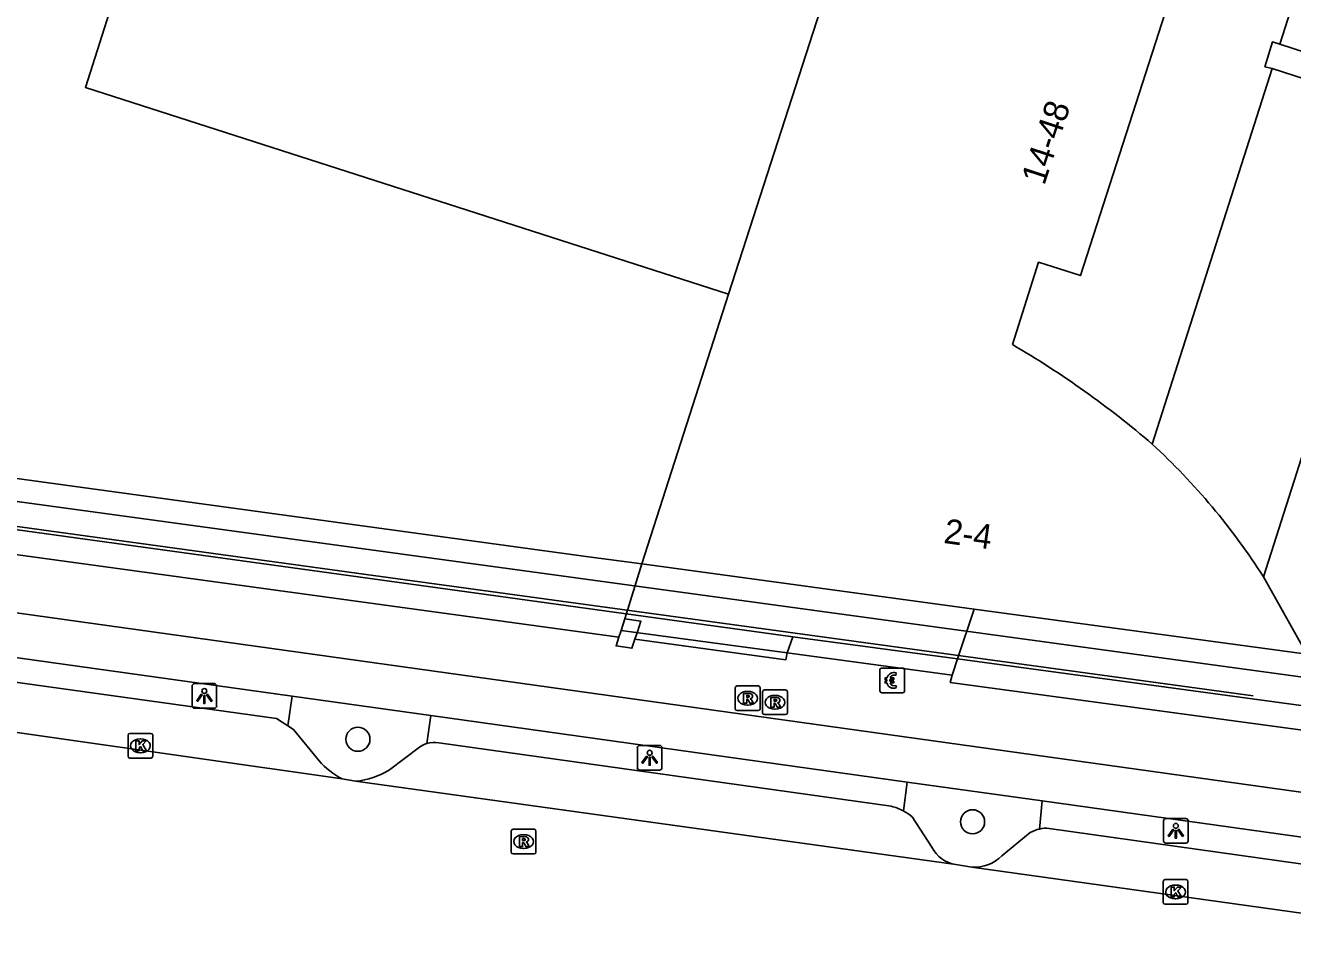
# Model space of a CAD drawing. Extents: x 160676 to 161153, y 383244 to 383713.
# Drawn here: x 160935.4 to 160986.7, y 383253.5 to 383290.1 of the extents above; entities that cross this region are included whole.
import ezdxf

# ---------------------------------------------------------------- set-up
doc = ezdxf.new("R2010")
doc.units = 0
for name, color, linetype in [('IMGEO_Berm_open', 7, 'Continuous'), ('IMGEO_Betaalautomaat', 7, 'Continuous'), ('IMGEO_Boom', 7, 'Continuous'), ('IMGEO_Fietspad_gesloten', 7, 'Continuous'), ('IMGEO_Kolk', 7, 'Continuous'), ('IMGEO_Lichtpunt', 7, 'Continuous'), ('IMGEO_Lijnafwatering', 7, 'Continuous'), ('IMGEO_Muur', 7, 'Continuous'), ('IMGEO_Pand', 7, 'Continuous'), ('IMGEO_Pand_nummerreeks', 7, 'Continuous'), ('IMGEO_Pand_overbouw', 7, 'Continuous'), ('IMGEO_Parkeervlak_open', 7, 'Continuous'), ('IMGEO_Rijbaan_lokaal_gesloten', 7, 'Continuous'), ('IMGEO_Rioolput', 7, 'Continuous'), ('IMGEO_Voetpad_open', 7, 'Continuous')]:
    doc.layers.add(name, color=color, linetype=linetype)

msp = doc.modelspace()

# ---------------------------------------------------------------- linework, layer by layer
at = {"layer": 'IMGEO_Berm_open'}
for points in [[(160946.189, 383262.908), (160946.008, 383261.707)], [(160951.638, 383260.989), (160951.803, 383262.123)], [(160971.094, 383259.424), (160970.944, 383258.256)], [(160976.455, 383257.521), (160976.57, 383258.658)]]:
    msp.add_lwpolyline(points, dxfattribs=at)
at = {"layer": 'IMGEO_Betaalautomaat'}
for p, q in [((160969.991, 383263.121), (160969.991, 383263.962)), ((160969.991, 383263.962), (160969.991, 383263.121)), ((160970.066, 383264.045), (160970.907, 383264.045)), ((160970.907, 383264.045), (160970.066, 383264.045)), ((160970.274, 383263.509), (160970.274, 383263.577)), ((160970.395, 383263.577), (160970.395, 383263.509)), ((160970.653, 383263.85), (160970.636, 383263.75)), ((160970.99, 383263.971), (160970.99, 383263.13)), ((160970.99, 383263.13), (160970.99, 383263.971)), ((160970.916, 383263.046), (160970.075, 383263.046)), ((160970.075, 383263.046), (160970.916, 383263.046)), ((160970.64, 383263.344), (160970.662, 383263.257))]:
    msp.add_line(p, q, dxfattribs=at)
for points in [[(160970.274, 383263.577), (160970.205, 383263.577), (160970.205, 383263.646), (160970.284, 383263.646)], [(160970.406, 383263.646), (160970.553, 383263.646), (160970.553, 383263.577), (160970.395, 383263.577)], [(160970.279, 383263.44), (160970.205, 383263.44), (160970.205, 383263.509), (160970.274, 383263.509)], [(160970.395, 383263.509), (160970.553, 383263.509), (160970.553, 383263.44), (160970.409, 383263.44)]]:
    msp.add_lwpolyline(points, dxfattribs=at)
for centre, radius, start, end in [((160970.069, 383263.968), 0.0779, 92.4484, 184.2845), ((160970.069, 383263.968), 0.0779, 92.4484, 184.2845), ((160970.567, 383263.57), 0.293, 73.014, 165.0139), ((160970.573, 383263.583), 0.179, 69.3236, 159.5683), ((160970.913, 383263.968), 0.0779, 2.4484, 94.2845), ((160970.913, 383263.968), 0.0779, 2.4484, 94.2845), ((160970.069, 383263.124), 0.0779, 182.4484, 274.2845), ((160970.069, 383263.124), 0.0779, 182.4484, 274.2845), ((160970.54, 383263.495), 0.267, 191.8096, 297.0389), ((160970.573, 383263.51), 0.179, 202.7625, 291.8693), ((160970.913, 383263.124), 0.0779, 272.4484, 4.2845), ((160970.913, 383263.124), 0.0779, 272.4484, 4.2845)]:
    msp.add_arc(centre, radius, start, end, dxfattribs=at)
at = {"layer": 'IMGEO_Boom'}
for centre in [(160948.846, 383261.16), (160973.749, 383257.813)]:
    msp.add_circle(centre, 0.489, dxfattribs=at)
at = {"layer": 'IMGEO_Fietspad_gesloten'}
for points in [[(160794.456, 383285.635), (160802.2, 383284.6), (160821.26, 383282.051), (160905.957, 383270.323), (160917.876, 383268.672), (161015.584, 383255.032)], [(160931.387, 383264.979), (160946.189, 383262.908)], [(160946.189, 383262.908), (160951.803, 383262.123)], [(160951.803, 383262.123), (160971.094, 383259.424)], [(160971.094, 383259.424), (160976.57, 383258.658)], [(160976.57, 383258.658), (160989.408, 383256.862)]]:
    msp.add_lwpolyline(points, dxfattribs=at)
at = {"layer": 'IMGEO_Kolk'}
for p, q in [((160939.535, 383260.469), (160939.535, 383261.321)), ((160939.61, 383261.395), (160940.462, 383261.395)), ((160940.023, 383261.175), (160940.048, 383261.175)), ((160940.536, 383261.321), (160940.536, 383260.469)), ((160940.046, 383260.615), (160940.021, 383260.615)), ((160940.462, 383260.395), (160939.61, 383260.395)), ((160981.472, 383254.544), (160981.472, 383255.396)), ((160981.547, 383255.47), (160982.399, 383255.47)), ((160982.473, 383255.396), (160982.473, 383254.544)), ((160981.96, 383255.25), (160981.985, 383255.25)), ((160982.399, 383254.47), (160981.547, 383254.47)), ((160981.983, 383254.69), (160981.958, 383254.69))]:
    msp.add_line(p, q, dxfattribs=at)
for points in [[(160939.535, 383260.469), (160939.535, 383261.321)], [(160939.61, 383261.395), (160940.462, 383261.395)], [(160939.856, 383261.095), (160939.979, 383261.095), (160939.979, 383260.944), (160940.109, 383261.095), (160940.273, 383261.095), (160940.127, 383260.944), (160940.28, 383260.695), (160940.128, 383260.695), (160940.043, 383260.859), (160939.979, 383260.792), (160939.979, 383260.695), (160939.856, 383260.695), (160939.856, 383261.095)], [(160940.536, 383261.321), (160940.536, 383260.469)], [(160940.462, 383260.395), (160939.61, 383260.395)], [(160981.472, 383254.544), (160981.472, 383255.396)], [(160981.547, 383255.47), (160982.399, 383255.47)], [(160982.473, 383255.396), (160982.473, 383254.544)], [(160981.793, 383255.17), (160981.916, 383255.17), (160981.916, 383255.019), (160982.046, 383255.17), (160982.21, 383255.17), (160982.064, 383255.019), (160982.217, 383254.77), (160982.065, 383254.77), (160981.98, 383254.934), (160981.916, 383254.867), (160981.916, 383254.77), (160981.793, 383254.77), (160981.793, 383255.17)], [(160982.399, 383254.47), (160981.547, 383254.47)]]:
    msp.add_lwpolyline(points, dxfattribs=at)
for centre, start, end in [((160939.612, 383261.319), 91.552, 178.448), ((160939.612, 383261.319), 91.552, 178.448), ((160940.46, 383261.319), 1.552, 88.448), ((160940.46, 383261.319), 1.552, 88.448), ((160939.612, 383260.471), 181.552, 268.448), ((160939.612, 383260.471), 181.552, 268.448), ((160940.46, 383260.471), 271.552, 358.448), ((160940.46, 383260.471), 271.552, 358.448), ((160981.549, 383255.394), 91.552, 178.448), ((160981.549, 383255.394), 91.552, 178.448), ((160982.397, 383255.394), 1.552, 88.448), ((160982.397, 383255.394), 1.552, 88.448), ((160981.549, 383254.546), 181.552, 268.448), ((160981.549, 383254.546), 181.552, 268.448), ((160982.397, 383254.546), 271.552, 358.448), ((160982.397, 383254.546), 271.552, 358.448)]:
    msp.add_arc(centre, 0.0765, start, end, dxfattribs=at)
for centre, major_axis, ratio, start_param, end_param in [((160940.022, 383260.895), (-0.387, 0.002), 0.722429, 4.712389, 7.853982), ((160940.047, 383260.895), (-0.39, 0.002), 0.717154, 1.570796, 4.712389), ((160981.959, 383254.97), (-0.387, 0.002), 0.722429, 4.712389, 7.853982), ((160981.984, 383254.97), (-0.39, 0.002), 0.717154, 1.570796, 4.712389)]:
    msp.add_ellipse(centre, major_axis=major_axis, ratio=ratio, start_param=start_param, end_param=end_param, dxfattribs=at)
at = {"layer": 'IMGEO_Lichtpunt'}
for p, q in [((160942.128, 383263.318), (160942.128, 383262.511)), ((160942.128, 383263.318), (160942.128, 383262.511)), ((160943.03, 383263.413), (160942.222, 383263.413)), ((160943.03, 383263.413), (160942.222, 383263.413)), ((160943.124, 383262.511), (160943.124, 383263.318)), ((160943.124, 383262.511), (160943.124, 383263.318)), ((160942.222, 383262.417), (160943.03, 383262.417)), ((160942.222, 383262.417), (160943.03, 383262.417)), ((160960.167, 383260.813), (160960.167, 383260.006)), ((160960.167, 383260.813), (160960.167, 383260.006)), ((160961.069, 383260.908), (160960.261, 383260.908)), ((160961.069, 383260.908), (160960.261, 383260.908)), ((160961.163, 383260.006), (160961.163, 383260.813)), ((160961.163, 383260.006), (160961.163, 383260.813)), ((160960.261, 383259.912), (160961.069, 383259.912)), ((160960.261, 383259.912), (160961.069, 383259.912)), ((160982.387, 383257.945), (160981.579, 383257.945)), ((160982.387, 383257.945), (160981.579, 383257.945)), ((160981.485, 383257.85), (160981.485, 383257.043)), ((160981.485, 383257.85), (160981.485, 383257.043)), ((160982.481, 383257.043), (160982.481, 383257.85)), ((160982.481, 383257.043), (160982.481, 383257.85)), ((160981.579, 383256.949), (160982.387, 383256.949)), ((160981.579, 383256.949), (160982.387, 383256.949))]:
    msp.add_line(p, q, dxfattribs=at)
for points in [[(160942.502, 383262.982), (160942.541, 383262.954), (160942.353, 383262.692), (160942.315, 383262.719), (160942.502, 383262.982)], [(160942.604, 383262.934), (160942.651, 383262.934), (160942.651, 383262.612), (160942.604, 383262.612), (160942.604, 383262.934)], [(160942.714, 383262.954), (160942.752, 383262.981), (160942.939, 383262.719), (160942.9, 383262.691), (160942.714, 383262.954)], [(160960.541, 383260.477), (160960.58, 383260.449), (160960.392, 383260.187), (160960.354, 383260.214), (160960.541, 383260.477)], [(160960.753, 383260.449), (160960.791, 383260.476), (160960.978, 383260.214), (160960.939, 383260.186), (160960.753, 383260.449)], [(160960.643, 383260.429), (160960.69, 383260.429), (160960.69, 383260.107), (160960.643, 383260.107), (160960.643, 383260.429)], [(160981.859, 383257.514), (160981.898, 383257.486), (160981.71, 383257.224), (160981.672, 383257.251), (160981.859, 383257.514)], [(160981.961, 383257.466), (160982.008, 383257.466), (160982.008, 383257.144), (160981.961, 383257.144), (160981.961, 383257.466)], [(160982.071, 383257.486), (160982.109, 383257.513), (160982.296, 383257.251), (160982.257, 383257.223), (160982.071, 383257.486)]]:
    msp.add_lwpolyline(points, dxfattribs=at)
for centre in [(160942.627, 383263.116), (160960.666, 383260.611), (160981.984, 383257.648)]:
    msp.add_circle(centre, 0.0994, dxfattribs=at)
for centre, start, end in [((160942.222, 383263.318), 90, 180), ((160942.222, 383263.318), 90, 180), ((160943.03, 383263.318), 0, 90), ((160943.03, 383263.318), 0, 90), ((160942.222, 383262.511), 180, 270), ((160942.222, 383262.511), 180, 270), ((160943.03, 383262.511), 270, 0), ((160943.03, 383262.511), 270, 360), ((160960.261, 383260.813), 90, 180), ((160960.261, 383260.813), 90, 180), ((160961.069, 383260.813), 0, 90), ((160961.069, 383260.813), 0, 90), ((160960.261, 383260.006), 180, 270), ((160960.261, 383260.006), 180, 270), ((160961.069, 383260.006), 270, 0), ((160961.069, 383260.006), 270, 360), ((160981.579, 383257.85), 90, 180), ((160981.579, 383257.85), 90, 180), ((160982.387, 383257.85), 0, 90), ((160982.387, 383257.85), 0, 90), ((160981.579, 383257.043), 180, 270), ((160981.579, 383257.043), 180, 270), ((160982.387, 383257.043), 270, 0), ((160982.387, 383257.043), 270, 360)]:
    msp.add_arc(centre, 0.0946, start, end, dxfattribs=at)
at = {"layer": 'IMGEO_Lijnafwatering'}
for points in [[(160949.181, 383267.844), (160931.212, 383270.307)], [(160967.149, 383265.381), (160949.181, 383267.844)], [(160985.118, 383262.918), (160967.149, 383265.381)]]:
    msp.add_lwpolyline(points, dxfattribs=at)
at = {"layer": 'IMGEO_Muur'}
for points in [[(160986.202, 383289.329), (160985.898, 383289.425), (160985.595, 383288.418), (160985.89, 383288.35)], [(160986.202, 383289.329), (160990.482, 383287.946)], [(160991.53, 383286.518), (160985.89, 383288.35)]]:
    msp.add_lwpolyline(points, dxfattribs=at)
at = {"layer": 'IMGEO_Pand'}
for points in [[(160963.866, 383279.201), (160937.804, 383287.581), (160939.448, 383292.73), (160938.625, 383292.988), (160940.143, 383297.716), (160940.991, 383297.445), (160941.191, 383298.065), (160940.32, 383298.343), (160941.73, 383302.736), (160942.578, 383302.465), (160942.777, 383303.077)], [(160968.854, 383294.685), (160963.866, 383279.201)], [(160975.365, 383277.155), (160976.425, 383280.494), (160978.117, 383279.956), (160981.552, 383290.599), (160977.592, 383291.879), (160977.719, 383292.257), (160977.324, 383292.384), (160977.178, 383291.927), (160973.174, 383293.215), (160973.324, 383293.671), (160972.929, 383293.801), (160972.807, 383293.43), (160968.854, 383294.685)], [(160960.344, 383268.267), (160963.866, 383279.201)], [(160906.652, 383275.617), (160920.037, 383273.784), (160958.187, 383268.56), (160960.344, 383268.267)], [(160960.344, 383268.267), (160973.818, 383266.439), (160987.295, 383264.611)], [(160985.535, 383267.741), (160987.295, 383264.611)], [(160960.071, 383265.21), (160960.171, 383265.509), (160960.315, 383265.94), (160959.664, 383266.036), (160959.51, 383265.564), (160959.423, 383265.299)], [(160960.071, 383265.21), (160959.949, 383264.845), (160959.305, 383264.94), (160959.423, 383265.299)], [(160966.461, 383265.316), (160966.242, 383264.66)], [(160973.144, 383264.419), (160966.461, 383265.316)], [(160972.925, 383263.763), (160966.242, 383264.66)], [(160972.925, 383263.763), (160973.144, 383264.419)]]:
    msp.add_lwpolyline(points, dxfattribs=at)
for centre, radius, start, end in [((160956.004, 383243.962), 38.427, 49.3669, 59.7456), ((160962.374, 383252.928), 27.493, 32.6026, 47.274)]:
    msp.add_arc(centre, radius, start, end, dxfattribs=at)
at = {"layer": 'IMGEO_Pand_overbouw'}
msp.add_lwpolyline([(160973.818, 383266.439), (160960.344, 383268.267), (160959.664, 383266.036), (160959.51, 383265.564), (160966.242, 383264.66), (160966.461, 383265.316), (160973.144, 383264.419)], close=True, dxfattribs=at)
at = {"layer": 'IMGEO_Parkeervlak_open'}
for points in [[(160946.008, 383261.707), (160945.542, 383262.006), (160933.685, 383263.646)], [(160946.008, 383261.707), (160946.238, 383261.56), (160947.276, 383260.282)], [(160970.455, 383258.441), (160952.119, 383261.02)], [(160951.342, 383260.833), (160950.129, 383259.921)], [(160971.301, 383258.02), (160972.094, 383256.787)], [(160988.756, 383255.864), (160976.85, 383257.547)], [(160974.933, 383256.431), (160976.086, 383257.377)]]:
    msp.add_lwpolyline(points, dxfattribs=at)
for centre, radius, start, end in [((160951.928, 383260.079), 0.955, 107.7036, 127.8773), ((160951.941, 383260.039), 0.997, 79.704, 107.6711), ((160949.729, 383262.458), 3.279, 221.5745, 242.3612), ((160948.423, 383262.692), 3.254, 275.6766, 301.615), ((160970.007, 383256.519), 1.974, 61.6658, 76.8886), ((160969.987, 383256.421), 2.069, 50.5977, 62.4677), ((160976.742, 383256.241), 1.311, 102.6316, 120.0042), ((160976.738, 383256.239), 1.313, 85.0978, 102.434), ((160973.279, 383257.392), 1.33, 207.0341, 261.231), ((160973.794, 383257.609), 1.639, 267.3166, 314.0431)]:
    msp.add_arc(centre, radius, start, end, dxfattribs=at)
at = {"layer": 'IMGEO_Rijbaan_lokaal_gesloten'}
for points in [[(160948.208, 383259.553), (160930.19, 383262.116)], [(160948.745, 383259.454), (160948.208, 383259.553)], [(160973.076, 383256.077), (160948.745, 383259.454)], [(160973.717, 383255.972), (160973.076, 383256.077)], [(160991.33, 383253.522), (160973.717, 383255.972)]]:
    msp.add_lwpolyline(points, dxfattribs=at)
at = {"layer": 'IMGEO_Rioolput'}
for p, q in [((160964.136, 383262.393), (160964.136, 383263.245)), ((160964.211, 383263.319), (160965.063, 383263.319)), ((160964.624, 383263.099), (160964.649, 383263.099)), ((160965.137, 383263.245), (160965.137, 383262.393)), ((160965.243, 383262.231), (160965.243, 383263.083)), ((160965.318, 383263.157), (160966.17, 383263.157)), ((160966.244, 383263.083), (160966.244, 383262.231)), ((160964.647, 383262.539), (160964.622, 383262.539)), ((160965.731, 383262.937), (160965.756, 383262.937)), ((160965.063, 383262.319), (160964.211, 383262.319)), ((160966.17, 383262.157), (160965.318, 383262.157)), ((160965.754, 383262.377), (160965.729, 383262.377)), ((160955.058, 383256.585), (160955.058, 383257.437)), ((160955.133, 383257.511), (160955.985, 383257.511)), ((160956.059, 383257.437), (160956.059, 383256.585)), ((160955.546, 383257.291), (160955.571, 383257.291)), ((160955.985, 383256.511), (160955.133, 383256.511)), ((160955.569, 383256.731), (160955.544, 383256.731))]:
    msp.add_line(p, q, dxfattribs=at)
for points in [[(160964.136, 383262.393), (160964.136, 383263.245)], [(160964.211, 383263.319), (160965.063, 383263.319)], [(160965.137, 383263.245), (160965.137, 383262.393)], [(160965.243, 383262.231), (160965.243, 383263.083)], [(160965.318, 383263.157), (160966.17, 383263.157)], [(160966.244, 383263.083), (160966.244, 383262.231)], [(160964.725, 383263.017), (160964.473, 383263.019), (160964.473, 383262.619)], [(160964.473, 383262.619), (160964.597, 383262.619), (160964.597, 383262.781), (160964.608, 383262.781)], [(160964.651, 383262.938), (160964.597, 383262.938), (160964.597, 383262.857)], [(160964.597, 383262.857), (160964.649, 383262.857)], [(160964.655, 383262.752), (160964.726, 383262.619), (160964.866, 383262.619), (160964.801, 383262.745)], [(160965.832, 383262.855), (160965.58, 383262.857), (160965.58, 383262.457)], [(160965.58, 383262.457), (160965.704, 383262.457), (160965.704, 383262.619), (160965.715, 383262.619)], [(160965.758, 383262.776), (160965.704, 383262.776), (160965.704, 383262.695)], [(160965.704, 383262.695), (160965.756, 383262.695)], [(160965.762, 383262.59), (160965.833, 383262.457), (160965.973, 383262.457), (160965.908, 383262.583)], [(160965.063, 383262.319), (160964.211, 383262.319)], [(160966.17, 383262.157), (160965.318, 383262.157)], [(160955.058, 383256.585), (160955.058, 383257.437)], [(160955.133, 383257.511), (160955.985, 383257.511)], [(160956.059, 383257.437), (160956.059, 383256.585)], [(160955.647, 383257.209), (160955.395, 383257.211), (160955.395, 383256.811)], [(160955.395, 383256.811), (160955.519, 383256.811), (160955.519, 383256.973), (160955.53, 383256.973)], [(160955.573, 383257.13), (160955.519, 383257.13), (160955.519, 383257.049)], [(160955.519, 383257.049), (160955.571, 383257.049)], [(160955.577, 383256.944), (160955.648, 383256.811), (160955.788, 383256.811), (160955.723, 383256.937)], [(160955.985, 383256.511), (160955.133, 383256.511)]]:
    msp.add_lwpolyline(points, dxfattribs=at)
for centre, radius, start, end in [((160964.213, 383263.243), 0.0765, 91.552, 178.448), ((160964.213, 383263.243), 0.0765, 91.552, 178.448), ((160965.061, 383263.243), 0.0765, 1.552, 88.448), ((160965.061, 383263.243), 0.0765, 1.552, 88.448), ((160965.32, 383263.081), 0.0765, 91.552, 178.448), ((160965.32, 383263.081), 0.0765, 91.552, 178.448), ((160966.168, 383263.081), 0.0765, 1.552, 88.448), ((160966.168, 383263.081), 0.0765, 1.552, 88.448), ((160964.607, 383262.728), 0.0533, 26.0293, 88.6989), ((160964.633, 383263.046), 0.19, 274.7715, 282.9687), ((160964.657, 383262.842), 0.0964, 77.0061, 93.1865), ((160964.671, 383262.899), 0.0378, 276.6634, 79.6772), ((160964.724, 383262.907), 0.109, 350.3612, 89.416), ((160964.722, 383262.907), 0.112, 277.5842, 350.9817), ((160964.706, 383262.692), 0.108, 29.5134, 73.7905), ((160965.714, 383262.566), 0.0533, 26.0293, 88.6989), ((160965.74, 383262.884), 0.19, 274.7715, 282.9687), ((160965.764, 383262.68), 0.0964, 77.0061, 93.1865), ((160965.778, 383262.737), 0.0378, 276.6634, 79.6772), ((160965.831, 383262.745), 0.109, 350.3612, 89.416), ((160965.829, 383262.745), 0.112, 277.5842, 350.9817), ((160965.813, 383262.53), 0.108, 29.5134, 73.7905), ((160964.213, 383262.395), 0.0765, 181.552, 268.448), ((160964.213, 383262.395), 0.0765, 181.552, 268.448), ((160965.061, 383262.395), 0.0765, 271.552, 358.448), ((160965.061, 383262.395), 0.0765, 271.552, 358.448), ((160965.32, 383262.233), 0.0765, 181.552, 268.448), ((160965.32, 383262.233), 0.0765, 181.552, 268.448), ((160966.168, 383262.233), 0.0765, 271.552, 358.448), ((160966.168, 383262.233), 0.0765, 271.552, 358.448), ((160955.135, 383257.435), 0.0765, 91.552, 178.448), ((160955.135, 383257.435), 0.0765, 91.552, 178.448), ((160955.983, 383257.435), 0.0765, 1.552, 88.448), ((160955.983, 383257.435), 0.0765, 1.552, 88.448), ((160955.529, 383256.92), 0.0533, 26.0293, 88.6989), ((160955.555, 383257.238), 0.19, 274.7715, 282.9687), ((160955.579, 383257.034), 0.0964, 77.0061, 93.1865), ((160955.593, 383257.091), 0.0378, 276.6634, 79.6772), ((160955.646, 383257.099), 0.109, 350.3612, 89.416), ((160955.644, 383257.099), 0.112, 277.5842, 350.9817), ((160955.628, 383256.884), 0.108, 29.5134, 73.7905), ((160955.135, 383256.587), 0.0765, 181.552, 268.448), ((160955.135, 383256.587), 0.0765, 181.552, 268.448), ((160955.983, 383256.587), 0.0765, 271.552, 358.448), ((160955.983, 383256.587), 0.0765, 271.552, 358.448)]:
    msp.add_arc(centre, radius, start, end, dxfattribs=at)
for centre, major_axis, ratio, start_param, end_param in [((160964.623, 383262.819), (-0.387, 0.002), 0.722429, 4.712389, 7.853982), ((160964.648, 383262.819), (-0.39, 0.002), 0.717154, 1.570796, 4.712389), ((160965.73, 383262.657), (-0.387, 0.002), 0.722429, 4.712389, 7.853982), ((160965.755, 383262.657), (-0.39, 0.002), 0.717154, 1.570796, 4.712389), ((160955.545, 383257.011), (-0.387, 0.002), 0.722429, 4.712389, 7.853982), ((160955.57, 383257.011), (-0.39, 0.002), 0.717154, 1.570796, 4.712389)]:
    msp.add_ellipse(centre, major_axis=major_axis, ratio=ratio, start_param=start_param, end_param=end_param, dxfattribs=at)
at = {"layer": 'IMGEO_Voetpad_open'}
for points in [[(160987.7, 383294.03), (160986.202, 383289.329)], [(160985.89, 383288.35), (160981.028, 383273.124)], [(160991.53, 383286.518), (160985.535, 383267.741)], [(160906.652, 383275.617), (160906.361, 383274.718), (160987.726, 383263.594)], [(160966.461, 383265.316), (160919.491, 383271.792), (160919.42, 383271.745)], [(160959.423, 383265.299), (160919.184, 383270.806), (160919.221, 383271.087)], [(160966.242, 383264.66), (160966.18, 383264.374), (160960.071, 383265.21)], [(160988.15, 383262.381), (160973.144, 383264.419)], [(160988.114, 383261.392), (160972.847, 383263.465), (160972.925, 383263.763)]]:
    msp.add_lwpolyline(points, dxfattribs=at)

# ---------------------------------------------------------------- texts
at = {"layer": 'IMGEO_Pand_nummerreeks'}
for s, rotation, p in [('14-48', 71.826, (160976.655, 383283.581)), ('2-4', 352.1849, (160972.548, 383269.119))]:
    msp.add_text(s, height=1, rotation=rotation, dxfattribs=at).set_placement(p)

doc.saveas('drawing.dxf')
